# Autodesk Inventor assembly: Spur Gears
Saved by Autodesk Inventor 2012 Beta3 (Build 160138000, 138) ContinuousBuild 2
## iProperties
Created: 2010-12
Part Number: Spur Gears
Document SubType Name: Assembly
Designer: Thom Tremblay
Categories: <?xml version="1.0" encoding="UTF-16"?> <MemberInstance><Categories><FamilyTemplate/><ParamToTemplateMap><ParamToTemplate><ParamToTemplate CategoryParameter="//
ClientObjectVersion: 1
Author: Thom Tremblay
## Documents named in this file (1)
- C:\Inventor 2012 Essentials\Assemblies\Chapter 6\c6-01\Design Accelerator\Spur Gears5.iam
